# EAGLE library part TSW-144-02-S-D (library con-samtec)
THROUGH-HOLE .025" SQ POST HEADER Source: Samtec TSW.pdf
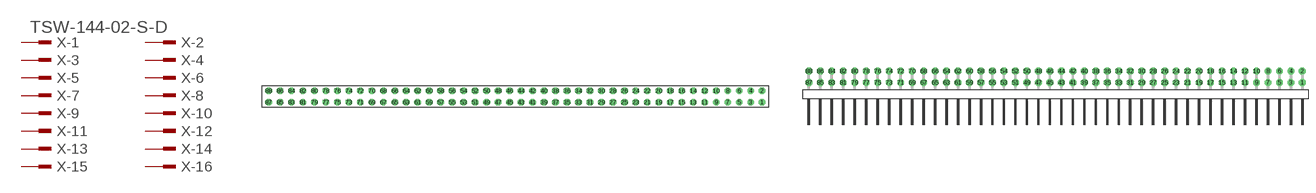
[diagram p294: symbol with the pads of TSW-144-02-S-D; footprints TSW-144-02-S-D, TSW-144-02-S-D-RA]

Designator prefix X; gates -1=MPINV -2=MPIN -3=MPIN -4=MPIN -5=MPIN -6=MPIN -7=MPIN -8=MPIN -9=MPIN -10=MPIN -11=MPIN -12=MPIN -13=MPIN -14=MPIN -15=MPIN -16=MPIN -17=MPIN -18=MPIN -19=MPIN -20=MPIN -21=MPIN -22=MPIN -23=MPIN -24=MPIN -25=MPIN -26=MPIN -27=MPIN -28=MPIN -29=MPIN -30=MPIN -31=MPIN -32=MPIN -33=MPIN -34=MPIN -35=MPIN -36=MPIN -37=MPIN -38=MPIN -39=MPIN -40=MPIN -41=MPIN -42=MPIN -43=MPIN -44=MPIN -45=MPIN -46=MPIN -47=MPIN -48=MPIN -49=MPIN -50=MPIN -51=MPIN -52=MPIN -53=MPIN -54=MPIN -55=MPIN -56=MPIN -57=MPIN -58=MPIN -59=MPIN -60=MPIN -61=MPIN -62=MPIN -63=MPIN -64=MPIN -65=MPIN -66=MPIN -67=MPIN -68=MPIN -69=MPIN -70=MPIN -71=MPIN -72=MPIN -73=MPIN -74=MPIN -75=MPIN -76=MPIN -77=MPIN -78=MPIN -79=MPIN -80=MPIN -81=MPIN -82=MPIN -83=MPIN -84=MPIN -85=MPIN -86=MPIN -87=MPIN -88=MPIN

## TSW-144-02-S-D (OC_FARNELL: unknown; OC_NEWARK: unknown)  [TSW-144-02-S-D]
1  -1:1  pas
2  -2:1  pas
3  -3:1  pas
4  -4:1  pas
5  -5:1  pas
6  -6:1  pas
7  -7:1  pas
8  -8:1  pas
9  -9:1  pas
10  -10:1  pas
11  -11:1  pas
12  -12:1  pas
13  -13:1  pas
14  -14:1  pas
15  -15:1  pas
16  -16:1  pas
17  -17:1  pas
18  -18:1  pas
19  -19:1  pas
20  -20:1  pas
21  -21:1  pas
22  -22:1  pas
23  -23:1  pas
24  -24:1  pas
25  -25:1  pas
26  -26:1  pas
27  -27:1  pas
28  -28:1  pas
29  -29:1  pas
30  -30:1  pas
31  -31:1  pas
32  -32:1  pas
33  -33:1  pas
34  -34:1  pas
35  -35:1  pas
36  -36:1  pas
37  -37:1  pas
38  -38:1  pas
39  -39:1  pas
40  -40:1  pas
41  -41:1  pas
42  -42:1  pas
43  -43:1  pas
44  -44:1  pas
45  -45:1  pas
46  -46:1  pas
47  -47:1  pas
48  -48:1  pas
49  -49:1  pas
50  -50:1  pas
51  -51:1  pas
52  -52:1  pas
53  -53:1  pas
54  -54:1  pas
55  -55:1  pas
56  -56:1  pas
57  -57:1  pas
58  -58:1  pas
59  -59:1  pas
60  -60:1  pas
61  -61:1  pas
62  -62:1  pas
63  -63:1  pas
64  -64:1  pas
65  -65:1  pas
66  -66:1  pas
67  -67:1  pas
68  -68:1  pas
69  -69:1  pas
70  -70:1  pas
71  -71:1  pas
72  -72:1  pas
73  -73:1  pas
74  -74:1  pas
75  -75:1  pas
76  -76:1  pas
77  -77:1  pas
78  -78:1  pas
79  -79:1  pas
80  -80:1  pas
81  -81:1  pas
82  -82:1  pas
83  -83:1  pas
84  -84:1  pas
85  -85:1  pas
86  -86:1  pas
87  -87:1  pas
88  -88:1  pas

## TSW-144-02-S-D-RA (OC_FARNELL: unknown; OC_NEWARK: unknown)  [TSW-144-02-S-D-RA]
Pads as for TSW-144-02-S-D

## Footprint TSW-144-02-S-D (pad centres in mm)
THROUGH-HOLE .025" SQ POST HEADER Source: Samtec TSW.pdf
drill 1 pad 1.5 octagon: 1 54.61,-1.27; 2 54.61,1.27; 3 52.07,-1.27; 4 52.07,1.27; 5 49.53,-1.27; 6 49.53,1.27; 7 46.99,-1.27; 8 46.99,1.27; 9 44.45,-1.27; 10 44.45,1.27; 11 41.91,-1.27; 12 41.91,1.27; 13 39.37,-1.27; 14 39.37,1.27; 15 36.83,-1.27; 16 36.83,1.27; 17 34.29,-1.27; 18 34.29,1.27; 19 31.75,-1.27; 20 31.75,1.27; 21 29.21,-1.27; 22 29.21,1.27; 23 26.67,-1.27; 24 26.67,1.27; 25 24.13,-1.27; 26 24.13,1.27; 27 21.59,-1.27; 28 21.59,1.27; 29 19.05,-1.27; 30 19.05,1.27; 31 16.51,-1.27; 32 16.51,1.27; 33 13.97,-1.27; 34 13.97,1.27; 35 11.43,-1.27; 36 11.43,1.27; 37 8.89,-1.27; 38 8.89,1.27; 39 6.35,-1.27; 40 6.35,1.27; 41 3.81,-1.27; 42 3.81,1.27; 43 1.27,-1.27; 44 1.27,1.27; 45 -1.27,-1.27; 46 -1.27,1.27; 47 -3.81,-1.27; 48 -3.81,1.27; 49 -6.35,-1.27; 50 -6.35,1.27; 51 -8.89,-1.27; 52 -8.89,1.27; 53 -11.43,-1.27; 54 -11.43,1.27; 55 -13.97,-1.27; 56 -13.97,1.27; 57 -16.51,-1.27; 58 -16.51,1.27; 59 -19.05,-1.27; 60 -19.05,1.27; 61 -21.59,-1.27; 62 -21.59,1.27; 63 -24.13,-1.27; 64 -24.13,1.27; 65 -26.67,-1.27; 66 -26.67,1.27; 67 -29.21,-1.27; 68 -29.21,1.27; 69 -31.75,-1.27; 70 -31.75,1.27; 71 -34.29,-1.27; 72 -34.29,1.27; 73 -36.83,-1.27; 74 -36.83,1.27; 75 -39.37,-1.27; 76 -39.37,1.27; 77 -41.91,-1.27; 78 -41.91,1.27; 79 -44.45,-1.27; 80 -44.45,1.27; 81 -46.99,-1.27; 82 -46.99,1.27; 83 -49.53,-1.27; 84 -49.53,1.27; 85 -52.07,-1.27; 86 -52.07,1.27; 87 -54.61,-1.27; 88 -54.61,1.27

## Footprint TSW-144-02-S-D-RA (pad centres in mm)
THROUGH-HOLE .025" SQ POST HEADER Source: Samtec TSW.pdf
drill 1 pad 1.5 octagon: 1 54.61,1.524; 2 54.61,4.064; 3 52.07,1.524; 4 52.07,4.064; 5 49.53,1.524; 6 49.53,4.064; 7 46.99,1.524; 8 46.99,4.064; 9 44.45,1.524; 10 44.45,4.064; 11 41.91,1.524; 12 41.91,4.064; 13 39.37,1.524; 14 39.37,4.064; 15 36.83,1.524; 16 36.83,4.064; 17 34.29,1.524; 18 34.29,4.064; 19 31.75,1.524; 20 31.75,4.064; 21 29.21,1.524; 22 29.21,4.064; 23 26.67,1.524; 24 26.67,4.064; 25 24.13,1.524; 26 24.13,4.064; 27 21.59,1.524; 28 21.59,4.064; 29 19.05,1.524; 30 19.05,4.064; 31 16.51,1.524; 32 16.51,4.064; 33 13.97,1.524; 34 13.97,4.064; 35 11.43,1.524; 36 11.43,4.064; 37 8.89,1.524; 38 8.89,4.064; 39 6.35,1.524; 40 6.35,4.064; 41 3.81,1.524; 42 3.81,4.064; 43 1.27,1.524; 44 1.27,4.064; 45 -1.27,1.524; 46 -1.27,4.064; 47 -3.81,1.524; 48 -3.81,4.064; 49 -6.35,1.524; 50 -6.35,4.064; 51 -8.89,1.524; 52 -8.89,4.064; 53 -11.43,1.524; 54 -11.43,4.064; 55 -13.97,1.524; 56 -13.97,4.064; 57 -16.51,1.524; 58 -16.51,4.064; 59 -19.05,1.524; 60 -19.05,4.064; 61 -21.59,1.524; 62 -21.59,4.064; 63 -24.13,1.524; 64 -24.13,4.064; 65 -26.67,1.524; 66 -26.67,4.064; 67 -29.21,1.524; 68 -29.21,4.064; 69 -31.75,1.524; 70 -31.75,4.064; 71 -34.29,1.524; 72 -34.29,4.064; 73 -36.83,1.524; 74 -36.83,4.064; 75 -39.37,1.524; 76 -39.37,4.064; 77 -41.91,1.524; 78 -41.91,4.064; 79 -44.45,1.524; 80 -44.45,4.064; 81 -46.99,1.524; 82 -46.99,4.064; 83 -49.53,1.524; 84 -49.53,4.064; 85 -52.07,1.524; 86 -52.07,4.064; 87 -54.61,1.524; 88 -54.61,4.064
